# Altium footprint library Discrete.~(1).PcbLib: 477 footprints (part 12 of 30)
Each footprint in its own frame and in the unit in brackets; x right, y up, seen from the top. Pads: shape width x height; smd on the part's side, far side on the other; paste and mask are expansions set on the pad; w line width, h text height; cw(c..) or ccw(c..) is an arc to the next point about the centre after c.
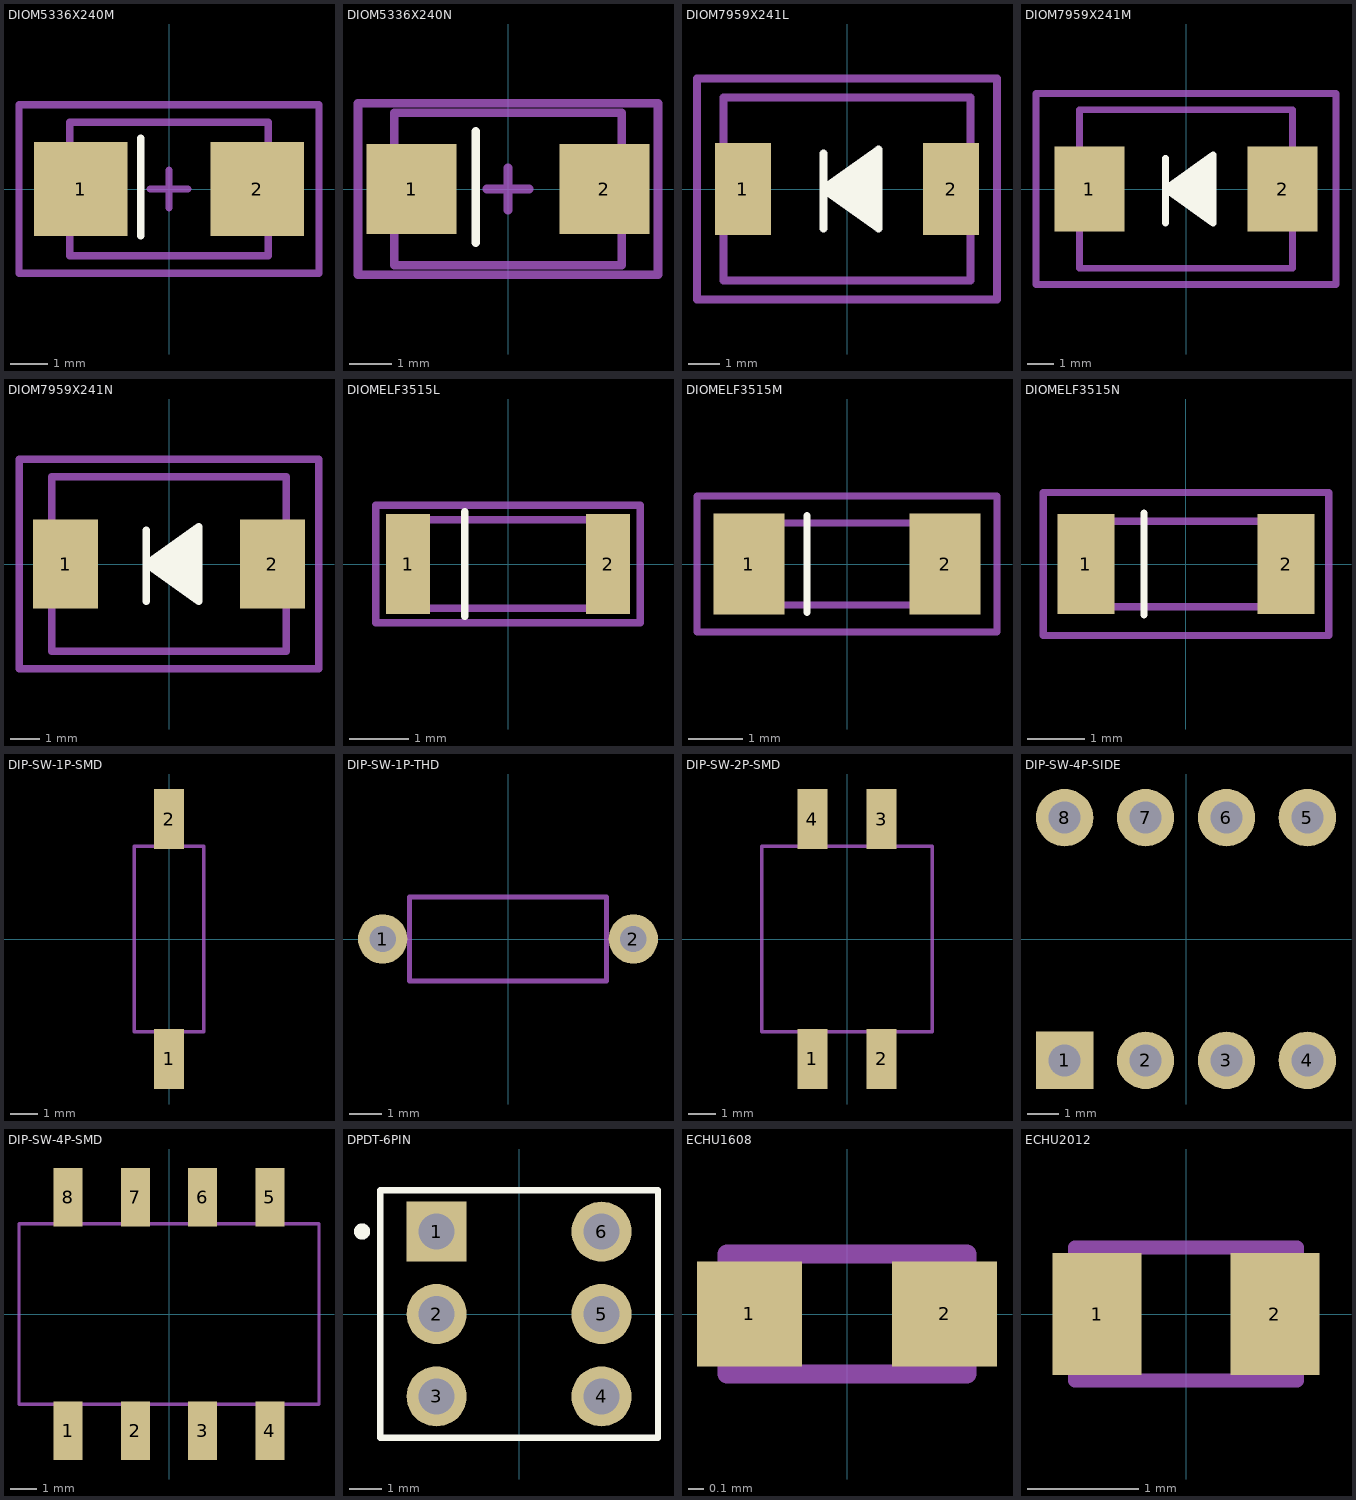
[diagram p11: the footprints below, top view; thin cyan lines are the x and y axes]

## DIOM5336X240M [mm] "Diode with Molded Body DO-214AA, SMB"
height 2.4
pads (2):
  rect 2.5x2.5 smd: 1(-2.35,0) 2(2.35,0)
Top Overlay:
  lines w0.2: -0.75,-1.25 -0.75,1.35
Mechanical 13:
  lines w0.2: -2.65,-1.775 -2.65,1.775 2.65,1.775 2.65,-1.775 -2.65,-1.775
Mechanical 15:
  lines w0.2: -0.5,0 0.5,0 ; 0,-0.5 0,0.5 ; -4,-2.25 -4,2.25 4,2.25 4,-2.25 -4,-2.25
3D body "SMB.STEP": height 2.35, standoff 0.04, extent -2.629,-1.8 2.675,1.8

## DIOM5336X240N [mm] "Diode with Molded Body DO-214AA, SMB"
height 2.4
pads (2):
  rect 2.1x2.1 smd: 1(-2.25,0) 2(2.25,0)
Top Overlay:
  lines w0.2: -0.75,-1.25 -0.75,1.35
Mechanical 13:
  lines w0.2: -2.65,-1.775 -2.65,1.775 2.65,1.775 2.65,-1.775 -2.65,-1.775
Mechanical 15:
  lines w0.2: -0.5,0 0.5,0 ; 0,-0.5 0,0.5 ; -3.5,-2 -3.5,2 3.5,2 3.5,-2 -3.5,-2
3D body "SMB.STEP": height 2.35, standoff 0.04, extent -2.629,-1.8 2.675,1.8

## DIOM7959X241L [mm] "Diode with Molded Body DO-214AB, SMC"
height 2.41
pads (2):
  rect 1.8x2.95 smd: 1(-3.35,0) 2(3.35,0)
Top Overlay:
  lines w0.254: -0.762,-1.27 -0.762,1.143 ; 0.737,0.127 0.229,0.051 0.635,-0.152 0.584,0.33 0,0.051 0.762,-0.483 0.711,0.66 -0.229,0 0.914,-0.762 0.889,0.965 -0.5,0 0.889,-0.991 ; -0.762,0 1.016,-1.27 1.016,1.27 -0.762,0
Mechanical 13:
  lines w0.254: -3.97,-2.95 -3.97,2.95 3.97,2.95 3.97,-2.95 -3.97,-2.95
Mechanical 15:
  lines w0.1: -0.5,0 0.5,0 ; 0,-0.5 0,0.5
  lines w0.254: -4.826,-3.556 -4.826,3.556 4.826,3.556 4.826,-3.556 -4.826,-3.556
3D body "SMC.STEP": height 2.45, standoff 0.03, extent -3.952,-2.9 3.952,2.9

## DIOM7959X241M [mm] "Diode with Molded Body DO-214AB, SMC"
height 2.41
pads (2):
  rect 2.6x3.15 smd: 1(-3.6,0) 2(3.6,0)
Top Overlay:
  lines w0.254: -0.762,-1.27 -0.762,1.143 ; 0.737,0.127 0.229,0.051 0.635,-0.152 0.584,0.33 0,0.051 0.762,-0.483 0.711,0.66 -0.229,0 0.914,-0.762 0.889,0.965 -0.5,0 0.889,-0.991 ; -0.762,0 1.016,1.27 1.016,-1.27 -0.762,0
Mechanical 13:
  lines w0.254: -3.97,-2.95 -3.97,2.95 3.97,2.95 3.97,-2.95 -3.97,-2.95
Mechanical 15:
  lines w0.254: -5.588,-3.556 -5.588,3.556 5.588,3.556 5.588,-3.556 -5.588,-3.556
3D body "SMC.STEP": height 2.45, standoff 0.03, extent -3.952,-2.9 3.952,2.9

## DIOM7959X241N [mm] "Diode with Molded Body DO-214AB, SMC"
height 2.41
pads (2):
  rect 2.2x3 smd: 1(-3.5,0) 2(3.5,0)
Top Overlay:
  lines w0.254: -0.762,-1.27 -0.762,1.143 ; 0.737,0.127 0.229,0.051 0.635,-0.152 0.584,0.33 0,0.051 0.762,-0.483 0.711,0.66 -0.229,0 0.914,-0.762 0.889,0.965 -0.5,0 0.889,-0.991 ; -0.762,0 1.016,-1.27 1.016,1.27 -0.762,0
Mechanical 13:
  lines w0.254: -3.97,-2.95 -3.97,2.95 3.97,2.95 3.97,-2.95 -3.97,-2.95
Mechanical 15:
  lines w0.254: -5.08,-3.556 -5.08,3.556 5.08,3.556 5.08,-3.556 -5.08,-3.556
3D body "SMC.STEP": height 2.45, standoff 0.03, extent -3.952,-2.9 3.952,2.9

## DIOMELF3515L [mm] "IEC 100H01, SOD-80C"
height 1.5
pads (2):
  rect 0.75x1.7 smd: 1(-1.7,0) 2(1.7,0)
Top Overlay:
  lines w0.127: -0.734,-0.889 -0.734,0.889
Mechanical 13:
  lines w0.127: -1.75,-0.75 1.75,-0.75 1.75,0.75 -1.75,0.75 -1.75,-0.75
Mechanical 15:
  lines w0.127: -2.25,-1 -2.25,1 2.25,1 2.25,-1 -2.25,-1
3D body: height 1.49, standoff 0, extent -1.775,-0.772 1.725,0.725

## DIOMELF3515M [mm] "IEC 100H01, SOD-80C"
height 1.5
pads (2):
  rect 1.3x1.85 smd: 1(-1.8,0) 2(1.8,0)
Top Overlay:
  lines w0.127: -0.734,-0.889 -0.734,0.889
Mechanical 13:
  lines w0.127: -1.75,-0.75 -1.75,0.75 1.75,0.75 1.75,-0.75 -1.75,-0.75
Mechanical 15:
  lines w0.127: -2.75,-1.25 2.75,-1.25 2.75,1.25 -2.75,1.25 -2.75,-1.25
3D body: height 1.49, standoff 0, extent -1.775,-0.772 1.725,0.725

## DIOMELF3515N [mm] "IEC 100H01, SOD-80C"
height 1.5
pads (2):
  rect 1x1.75 smd: 1(-1.75,0) 2(1.75,0)
Top Overlay:
  lines w0.127: -0.734,-0.889 -0.734,0.889
Mechanical 13:
  lines w0.127: -1.75,-0.75 1.75,-0.75 1.75,0.75 -1.75,0.75 -1.75,-0.75
Mechanical 15:
  lines w0.127: -2.5,-1.25 -2.5,1.25 2.5,1.25 2.5,-1.25 -2.5,-1.25
3D body: height 1.49, standoff 0, extent -1.775,-0.772 1.725,0.725

## DIP-SW-1P-SMD [mm]
pads (2):
  rect 1.1x2.2 smd: 1(0,-4.4) 2(0,4.4)
Mechanical 13:
  lines w0.127: -1.27,-3.4 1.27,-3.4 1.27,3.4 -1.27,3.4 -1.27,-3.4
3D body: height 3.9, standoff 0, extent -1.27,-3.4 1.27,3.4
3D body: height 4.5, standoff 0, extent -0.508,-2.032 0.508,-0.508

## DIP-SW-1P-THD [mm]
pads (2):
  round 1.5 hole 0.8: 1(-3.81,0) 2(3.81,0)
Mechanical 13:
  lines w0.152: -3,-1.27 3,-1.27 3,1.27 -3,1.27 -3,-1.27
3D body: height 3.6, standoff 0, extent -3,-1.27 3,1.27

## DIP-SW-2P-SMD [mm]
pads (4):
  rect 1.1x2.2 smd: 1(-1.27,-4.4) 2(1.27,-4.4) 3(1.27,4.4) 4(-1.27,4.4)
Mechanical 13:
  lines w0.127: 3.1,-3.4 -3.12,-3.4 -3.12,3.4 3.1,3.4 ; 3.12,-3.4 3.12,3.4
3D body: height 4.5, standoff 0, extent 0.762,-2.032 1.778,-0.508
3D body: height 4.5, standoff 0, extent -1.778,-2.032 -0.762,-0.508
3D body: height 3.9, standoff 0, extent -3.12,-3.4 3.24,3.4

## DIP-SW-4P-SIDE [mm]
pads (8):
  rect 1.8x1.8 hole 1: 1(-3.81,-3.81)
  round 1.8 hole 1: 2(-1.27,-3.81) 3(1.27,-3.81) 4(3.81,-3.81) 5(3.81,3.81) 6(1.27,3.81) 7(-1.27,3.81) 8(-3.81,3.81)
3D body "c-1-5435802-5-b-3d.stp": height 7.5, standoff -3.3, extent -6.095,-4.83 6.095,4.825

## DIP-SW-4P-SMD [mm]
pads (8):
  rect 1.1x2.2 smd: 1(-3.81,-4.4) 2(-1.27,-4.4) 3(1.27,-4.4) 4(3.81,-4.4) 5(3.81,4.4) 6(1.27,4.4) 7(-1.27,4.4) 8(-3.81,4.4)
Mechanical 13:
  lines w0.127: -5.66,-3.4 -5.66,3.4 5.66,3.4 5.66,-3.4 -5.66,-3.4
3D body: height 4.5, standoff 0, extent 0.762,-2.032 1.778,-0.508
3D body: height 4.5, standoff 0, extent 3.302,-2.032 4.318,-0.508
3D body: height 4.5, standoff 0, extent -1.778,-2.032 -0.762,-0.508
3D body: height 4.5, standoff 0, extent -4.318,-2.032 -3.302,-0.508
3D body: height 3.9, standoff 0, extent -5.66,-3.4 5.66,3.4

## DPDT-6PIN [mm] "Double-Pole, Double-Throw Switch; 6 Leads"
pads (6):
  rect 1.85x1.85 hole 1.1: 1(-2.54,2.54)
  round 1.85 hole 1.1: 2(-2.54,0) 3(-2.54,-2.54) 4(2.54,-2.54) 5(2.54,0) 6(2.54,2.54)
Top Overlay:
  circle w0.25: c-4.836,2.541 r0.125
  lines w0.2: -4.28,-3.81 -4.28,3.81 4.28,3.81 4.28,-3.81 -4.28,-3.81

## ECHU1608 [mm]
height 0.6
pads (2):
  rect 0.7x0.7 smd: 1(-0.65,0) 2(0.65,0)
Mechanical 13:
  lines w0.127: -0.8,-0.4 0.8,-0.4 0.8,0.4 -0.8,0.4 -0.8,-0.4
3D body: height 0.7, standoff 0, extent -0.8,-0.4 0.8,0.4

## ECHU2012 [mm]
height 0.9
pads (2):
  rect 0.8x1.1 smd: 1(-0.8,0) 2(0.8,0)
Mechanical 13:
  lines w0.127: -1,-0.6 -1,0.6 1,0.6 1,-0.6 -1,-0.6
3D body: height 0.9, standoff 0, extent -1,-0.6 1,0.6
